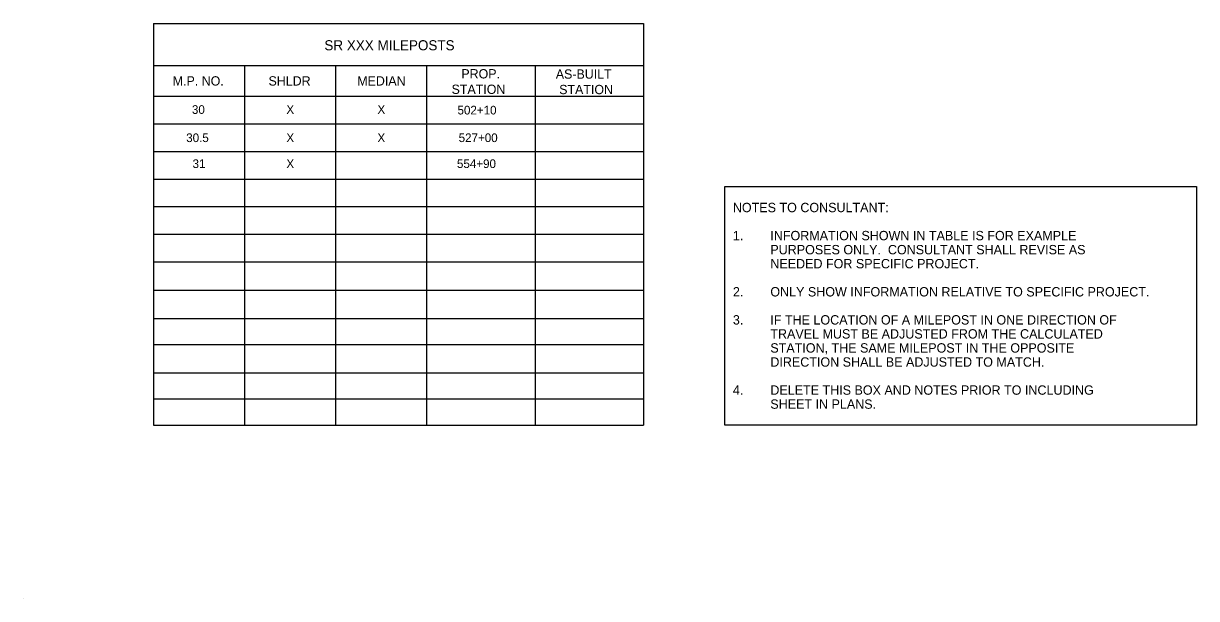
# Model space of a CAD drawing. Extents: x 56108 to 56734, y 11696 to 12110.
# Drawn here: x 56107.9 to 56486.8, y 11696.3 to 11882.1 of the extents above; entities that cross this region are included whole.
import ezdxf

# ---------------------------------------------------------------- set-up
doc = ezdxf.new("R2010")
doc.units = 0
for name, color, linetype in [('AdhocPoint_dp', 7, 'Continuous'), ('TextAlert', 7, 'Continuous'), ('TextTables', 7, 'Continuous')]:
    doc.layers.add(name, color=color, linetype=linetype)

msp = doc.modelspace()

# ---------------------------------------------------------------- linework, layer by layer
at = {"layer": 'AdhocPoint_dp'}
msp.add_line((56107.89, 11696.32), (56107.89, 11696.32), dxfattribs=at)
at = {"layer": 'TextAlert'}
msp.add_lwpolyline([(56334.41, 11829.47), (56486.79, 11829.47), (56486.79, 11752.32), (56334.41, 11752.32)], close=True, dxfattribs=at)
at = {"layer": 'TextTables'}
for p, q in [((56149.89, 11882.09), (56149.89, 11752.32)), ((56149.89, 11882.09), (56308.12, 11882.09)), ((56308.12, 11882.09), (56308.12, 11752.32)), ((56149.89, 11868.55), (56308.12, 11868.55)), ((56179.3, 11868.55), (56179.3, 11752.32)), ((56208.71, 11868.55), (56208.71, 11752.32)), ((56238.12, 11868.55), (56238.12, 11752.32)), ((56273.12, 11868.55), (56273.12, 11752.32)), ((56149.89, 11858.55), (56308.12, 11858.55)), ((56149.89, 11849.65), (56308.12, 11849.65)), ((56149.89, 11840.74), (56308.12, 11840.74)), ((56149.89, 11831.84), (56308.12, 11831.84)), ((56149.89, 11822.93), (56308.12, 11822.93)), ((56149.89, 11814.03), (56308.12, 11814.03)), ((56149.89, 11805.12), (56308.12, 11805.12)), ((56149.89, 11795.98), (56308.12, 11795.98)), ((56149.89, 11786.82), (56308.12, 11786.82)), ((56149.89, 11778.34), (56308.12, 11778.34)), ((56149.89, 11769.26), (56308.12, 11769.26)), ((56149.89, 11760.79), (56308.12, 11760.79)), ((56149.89, 11752.32), (56308.12, 11752.32))]:
    msp.add_line(p, q, dxfattribs=at)

# ---------------------------------------------------------------- texts
at = {"layer": 'TextAlert'}
for s, p in [('NOTES TO CONSULTANT:', (56337.03, 11821.12)), ('1.', (56337.03, 11812.05)), ('INFORMATION SHOWN IN TABLE IS FOR EXAMPLE ', (56349.13, 11812.05)), ('PURPOSES ONLY.  CONSULTANT SHALL REVISE AS', (56349.13, 11807.51)), ('NEEDED FOR SPECIFIC PROJECT.', (56349.13, 11802.98)), ('2.', (56337.03, 11793.9)), ('ONLY SHOW INFORMATION RELATIVE TO SPECIFIC PROJECT.', (56349.13, 11793.9)), ('3.', (56337.03, 11784.83)), ('IF THE LOCATION OF A MILEPOST IN ONE DIRECTION OF', (56349.13, 11784.83)), ('TRAVEL MUST BE ADJUSTED FROM THE CALCULATED', (56349.13, 11780.3)), ('STATION, THE SAME MILEPOST IN THE OPPOSITE', (56349.13, 11775.76)), ('DIRECTION SHALL BE ADJUSTED TO MATCH.', (56349.13, 11771.22)), ('4.', (56337.03, 11762.15)), ('DELETE THIS BOX AND NOTES PRIOR TO INCLUDING ', (56349.13, 11762.15)), ('SHEET IN PLANS.', (56349.13, 11757.62))]:
    msp.add_text(s, height=3.024, dxfattribs=at).set_placement(p)
at = {"layer": 'TextTables'}
for s, height, p in [('SR XXX MILEPOSTS', 3.2524, (56205.09, 11873.42)), ('PROP.', 3, (56249.33, 11864.33)), ('M.P. NO.', 3, (56156.1, 11862.03)), ('SHLDR', 3, (56187.04, 11862.03)), ('MEDIAN', 3, (56215.71, 11862.03)), ('AS-BUILT', 3, (56279.83, 11864.25)), ('STATION', 3, (56246.17, 11859.33)), ('STATION', 3, (56280.93, 11859.25))]:
    msp.add_text(s, height=height, dxfattribs=at).set_placement(p)
for s, p in [('30', (56162.3, 11852.88)), ('X', (56192.82, 11852.88)), ('X', (56222.23, 11852.88)), ('502+10', (56248.09, 11852.69)), ('30.5', (56160.46, 11843.77)), ('X', (56192.82, 11843.77)), ('X', (56222.23, 11843.77)), ('527+00', (56248.46, 11843.77)), ('31', (56162.51, 11835.39)), ('X', (56192.82, 11835.39)), ('554+90', (56247.91, 11835.39))]:
    msp.add_text(s, height=2.8, rotation=360, dxfattribs=at).set_placement(p)

doc.saveas('drawing.dxf')
